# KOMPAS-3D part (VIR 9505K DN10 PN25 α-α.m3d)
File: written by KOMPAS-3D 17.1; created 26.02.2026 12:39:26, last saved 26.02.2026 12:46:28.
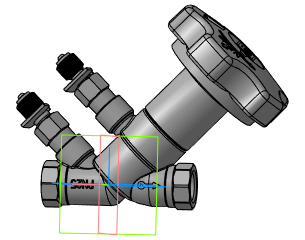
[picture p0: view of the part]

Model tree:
1. Операция без истории:4  (labels: VIR 9505K DN10 PN25 р-р)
